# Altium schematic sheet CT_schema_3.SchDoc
size 300 x 247 mm
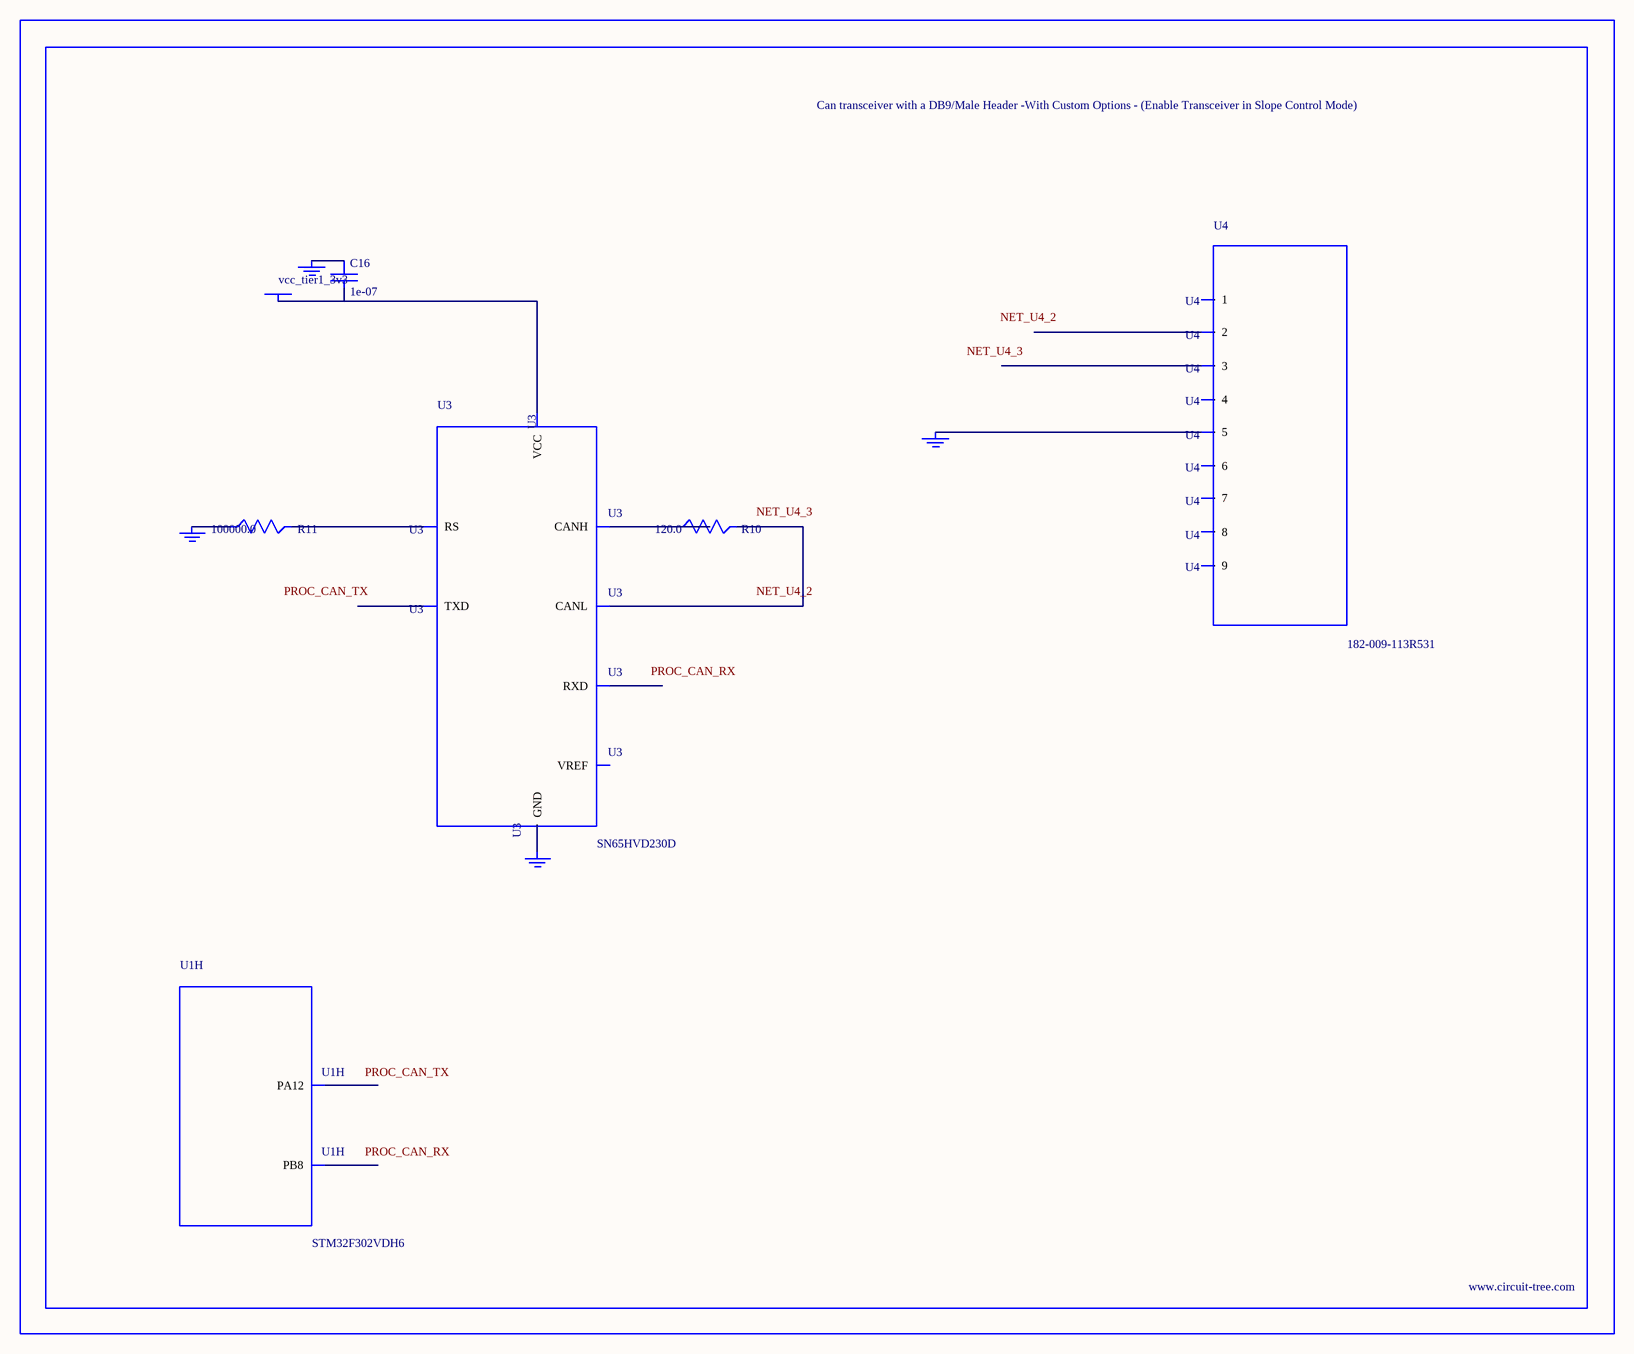
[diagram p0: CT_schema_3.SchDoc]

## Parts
BORDER2  (no value)
C16  1e-07  [C0402]
GND_INSTANCE_2_0  (no value)
GND_INSTANCE_2_1  (no value)
GND_INSTANCE_2_2  (no value)
GND_INSTANCE_2_3  (no value)
POWER_INSTANCE_2_0  vcc_tier1_3v3
R10  120.0  [R0603]
R11  100000.0  [R0603]
U1  STM32F302VDH6  [UFBGA100]  (part H of 9)
U3  SN65HVD230D  [SOIC-8]
U4  182-009-113R531  [182-009-MALE]

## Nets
NetC16_1: C16.1 GND_INSTANCE_2_0.0(GND)
NetC16_2: C16.2 POWER_INSTANCE_2_0.0(PWR) U3.3(VCC)
NetGND_INSTANCE_2_1_0: GND_INSTANCE_2_1.0(GND) R11.1
NetGND_INSTANCE_2_2_0: GND_INSTANCE_2_2.0(GND) U3.2(GND)
NetGND_INSTANCE_2_3_0: GND_INSTANCE_2_3.0(GND) U4.5
NetR10_1: R10.1 U3.7(CANH)
NetR10_2: R10.2 U3.6(CANL)
NetR11_2: R11.2 U3.8(RS)

Not connected (* = marked no-connect by the designer): U1 A3(PB8) A12(PA12); U3 1(TXD) 4(RXD) 5(VREF); U4 1 2 3 4 6 7 8 9

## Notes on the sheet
- Labels drawn without touching a wire or pin: NET_U4_2, NET_U4_3, PROC_CAN_RX, PROC_CAN_TX

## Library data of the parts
BORDER2 = BORDER_PAGE2
C16 = C0402C104K3RACTU
GND_INSTANCE_2_0-GND_INSTANCE_2_3 = GND
POWER_INSTANCE_2_0 = PWR
R10 = RC0603JR-07120RL
R11 = RC0603JR-07100KL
